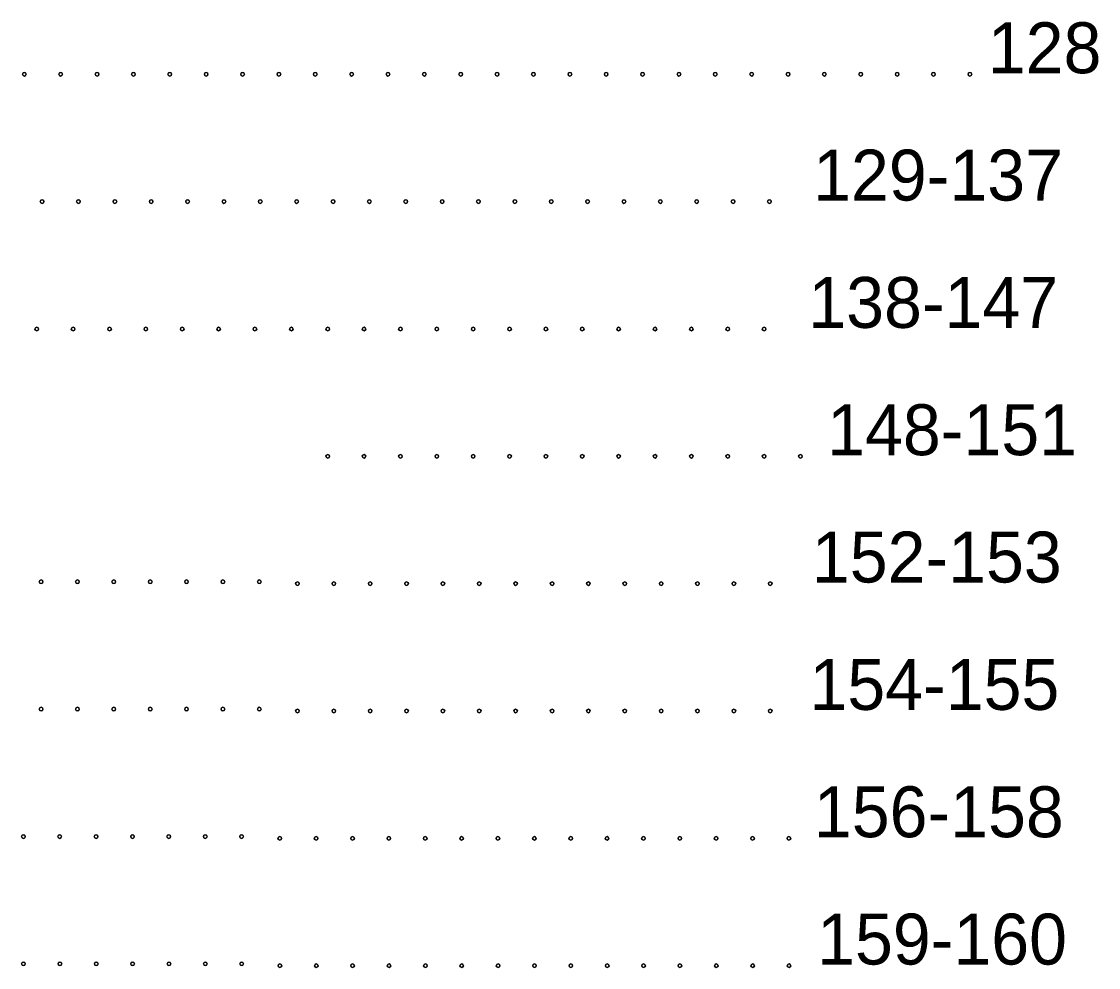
# Model space of a CAD drawing. Extents: x 0 to 1.42, y 0 to 0.92.
# Drawn here: x 0.7967 to 0.9201, y 0.5818 to 0.6902 of the extents above; entities that cross this region are included whole.
import ezdxf

# ---------------------------------------------------------------- set-up
doc = ezdxf.new("R2010")
doc.units = 0
doc.layers.add('DRAFT_Text-Notes', color=7, linetype='Continuous')

msp = doc.modelspace()

# ---------------------------------------------------------------- linework, layer by layer
at = {"layer": 'DRAFT_Text-Notes'}
for centre in [(0.79703, 0.68418), (0.80119, 0.68418), (0.80536, 0.68418), (0.80953, 0.68418), (0.81369, 0.68418), (0.81786, 0.68418), (0.82203, 0.68418), (0.82619, 0.68418), (0.83036, 0.68418), (0.83453, 0.68418), (0.83869, 0.68418), (0.84286, 0.68418), (0.84703, 0.68418), (0.85119, 0.68418), (0.85536, 0.68418), (0.85953, 0.68418), (0.86369, 0.68418), (0.86786, 0.68418), (0.87203, 0.68418), (0.87619, 0.68418), (0.88036, 0.68418), (0.88453, 0.68418), (0.88869, 0.68418), (0.89286, 0.68418), (0.89703, 0.68418), (0.90119, 0.68418), (0.90536, 0.68418), (0.79906, 0.66959), (0.80323, 0.66959), (0.8074, 0.66959), (0.81156, 0.66959), (0.81573, 0.66959), (0.8199, 0.66959), (0.82406, 0.66959), (0.82823, 0.66959), (0.8324, 0.66959), (0.83656, 0.66959), (0.84073, 0.66959), (0.8449, 0.66959), (0.84906, 0.66959), (0.85323, 0.66959), (0.8574, 0.66959), (0.86156, 0.66959), (0.86573, 0.66959), (0.8699, 0.66959), (0.87406, 0.66959), (0.87823, 0.66959), (0.8824, 0.66959), (0.79845, 0.65499), (0.80262, 0.65499), (0.80679, 0.65499), (0.81095, 0.65499), (0.81512, 0.65499), (0.81929, 0.65499), (0.82345, 0.65499), (0.82762, 0.65499), (0.83179, 0.65499), (0.83595, 0.65499), (0.84012, 0.65499), (0.84429, 0.65499), (0.84845, 0.65499), (0.85262, 0.65499), (0.85679, 0.65499), (0.86095, 0.65499), (0.86512, 0.65499), (0.86929, 0.65499), (0.87345, 0.65499), (0.87762, 0.65499), (0.88179, 0.65499), (0.83179, 0.6404), (0.83595, 0.6404), (0.84012, 0.6404), (0.84429, 0.6404), (0.84845, 0.6404), (0.85262, 0.6404), (0.85679, 0.6404), (0.86095, 0.6404), (0.86512, 0.6404), (0.86929, 0.6404), (0.87345, 0.6404), (0.87762, 0.6404), (0.88179, 0.6404), (0.88595, 0.6404), (0.79895, 0.62602), (0.80311, 0.62602), (0.80728, 0.62602), (0.81145, 0.62602), (0.81561, 0.62602), (0.81978, 0.62602), (0.82395, 0.62602), (0.82832, 0.62581), (0.83249, 0.62581), (0.83665, 0.62581), (0.84082, 0.62581), (0.84499, 0.62581), (0.84915, 0.62581), (0.85332, 0.62581), (0.85749, 0.62581), (0.86165, 0.62581), (0.86582, 0.62581), (0.86999, 0.62581), (0.87415, 0.62581), (0.87832, 0.62581), (0.88249, 0.62581), (0.79895, 0.61143), (0.80311, 0.61143), (0.80728, 0.61143), (0.81145, 0.61143), (0.81561, 0.61143), (0.81978, 0.61143), (0.82395, 0.61143), (0.82832, 0.61122), (0.83249, 0.61122), (0.83665, 0.61122), (0.84082, 0.61122), (0.84499, 0.61122), (0.84915, 0.61122), (0.85332, 0.61122), (0.85749, 0.61122), (0.86165, 0.61122), (0.86582, 0.61122), (0.86999, 0.61122), (0.87415, 0.61122), (0.87832, 0.61122), (0.88249, 0.61122), (0.79692, 0.59683), (0.80108, 0.59683), (0.80525, 0.59683), (0.80942, 0.59683), (0.81358, 0.59683), (0.81775, 0.59683), (0.82192, 0.59683), (0.82629, 0.59662), (0.83046, 0.59662), (0.83463, 0.59662), (0.83879, 0.59662), (0.84296, 0.59662), (0.84713, 0.59662), (0.85129, 0.59662), (0.85546, 0.59662), (0.85963, 0.59662), (0.86379, 0.59662), (0.86796, 0.59662), (0.87213, 0.59662), (0.87629, 0.59662), (0.88046, 0.59662), (0.88463, 0.59662), (0.79693, 0.58224), (0.8011, 0.58224), (0.80527, 0.58224), (0.80943, 0.58224), (0.8136, 0.58224), (0.81777, 0.58224), (0.82193, 0.58224), (0.82631, 0.58203), (0.83048, 0.58203), (0.83464, 0.58203), (0.83881, 0.58203), (0.84298, 0.58203), (0.84714, 0.58203), (0.85131, 0.58203), (0.85548, 0.58203), (0.85964, 0.58203), (0.86381, 0.58203), (0.86798, 0.58203), (0.87214, 0.58203), (0.87631, 0.58203), (0.88048, 0.58203), (0.88464, 0.58203)]:
    msp.add_circle(centre, 0.000208, dxfattribs=at)
for centre, start, end in [((0.79703, 0.68418), 0, 180), ((0.79703, 0.68418), 180, 0), ((0.80119, 0.68418), 0, 180), ((0.80119, 0.68418), 180, 0), ((0.80536, 0.68418), 0, 180), ((0.80536, 0.68418), 180, 0), ((0.80953, 0.68418), 0, 180), ((0.80953, 0.68418), 180, 0), ((0.81369, 0.68418), 0, 180), ((0.81369, 0.68418), 180, 0), ((0.81786, 0.68418), 0, 180), ((0.81786, 0.68418), 180, 0), ((0.82203, 0.68418), 0, 180), ((0.82203, 0.68418), 180, 0), ((0.82619, 0.68418), 0, 180), ((0.82619, 0.68418), 180, 0), ((0.83036, 0.68418), 0, 180), ((0.83036, 0.68418), 180, 0), ((0.83453, 0.68418), 0, 180), ((0.83453, 0.68418), 180, 0), ((0.83869, 0.68418), 0, 180), ((0.83869, 0.68418), 180, 0), ((0.84286, 0.68418), 0, 180), ((0.84286, 0.68418), 180, 0), ((0.84703, 0.68418), 0, 180), ((0.84703, 0.68418), 180, 0), ((0.85119, 0.68418), 0, 180), ((0.85119, 0.68418), 180, 0), ((0.85536, 0.68418), 0, 180), ((0.85536, 0.68418), 180, 0), ((0.85953, 0.68418), 0, 180), ((0.85953, 0.68418), 180, 0), ((0.86369, 0.68418), 0, 180), ((0.86369, 0.68418), 180, 0), ((0.86786, 0.68418), 0, 180), ((0.86786, 0.68418), 180, 0), ((0.87203, 0.68418), 0, 180), ((0.87203, 0.68418), 180, 0), ((0.87619, 0.68418), 0, 180), ((0.87619, 0.68418), 180, 0), ((0.88036, 0.68418), 0, 180), ((0.88036, 0.68418), 180, 0), ((0.88453, 0.68418), 0, 180), ((0.88453, 0.68418), 180, 0), ((0.88869, 0.68418), 0, 180), ((0.88869, 0.68418), 180, 0), ((0.89286, 0.68418), 0, 180), ((0.89286, 0.68418), 180, 0), ((0.89703, 0.68418), 0, 180), ((0.89703, 0.68418), 180, 0), ((0.90119, 0.68418), 0, 180), ((0.90119, 0.68418), 180, 0), ((0.90536, 0.68418), 0, 180), ((0.90536, 0.68418), 180, 0), ((0.79906, 0.66959), 0, 180), ((0.79906, 0.66959), 180, 0), ((0.80323, 0.66959), 0, 180), ((0.80323, 0.66959), 180, 0), ((0.8074, 0.66959), 0, 180), ((0.8074, 0.66959), 180, 0), ((0.81156, 0.66959), 0, 180), ((0.81156, 0.66959), 180, 0), ((0.81573, 0.66959), 0, 180), ((0.81573, 0.66959), 180, 0), ((0.8199, 0.66959), 0, 180), ((0.8199, 0.66959), 180, 0), ((0.82406, 0.66959), 0, 180), ((0.82406, 0.66959), 180, 0), ((0.82823, 0.66959), 0, 180), ((0.82823, 0.66959), 180, 0), ((0.8324, 0.66959), 0, 180), ((0.8324, 0.66959), 180, 0), ((0.83656, 0.66959), 0, 180), ((0.83656, 0.66959), 180, 0), ((0.84073, 0.66959), 0, 180), ((0.84073, 0.66959), 180, 0), ((0.8449, 0.66959), 0, 180), ((0.8449, 0.66959), 180, 0), ((0.84906, 0.66959), 0, 180), ((0.84906, 0.66959), 180, 0), ((0.85323, 0.66959), 0, 180), ((0.85323, 0.66959), 180, 0), ((0.8574, 0.66959), 0, 180), ((0.8574, 0.66959), 180, 0), ((0.86156, 0.66959), 0, 180), ((0.86156, 0.66959), 180, 0), ((0.86573, 0.66959), 0, 180), ((0.86573, 0.66959), 180, 0), ((0.8699, 0.66959), 0, 180), ((0.8699, 0.66959), 180, 0), ((0.87406, 0.66959), 0, 180), ((0.87406, 0.66959), 180, 0), ((0.87823, 0.66959), 0, 180), ((0.87823, 0.66959), 180, 0), ((0.8824, 0.66959), 0, 180), ((0.8824, 0.66959), 180, 0), ((0.79845, 0.65499), 0, 180), ((0.80262, 0.65499), 0, 180), ((0.80679, 0.65499), 0, 180), ((0.81095, 0.65499), 0, 180), ((0.81512, 0.65499), 0, 180), ((0.81929, 0.65499), 0, 180), ((0.82345, 0.65499), 0, 180), ((0.82762, 0.65499), 0, 180), ((0.83179, 0.65499), 0, 180), ((0.83595, 0.65499), 0, 180), ((0.84012, 0.65499), 0, 180), ((0.84429, 0.65499), 0, 180), ((0.84845, 0.65499), 0, 180), ((0.85262, 0.65499), 0, 180), ((0.85679, 0.65499), 0, 180), ((0.86095, 0.65499), 0, 180), ((0.86512, 0.65499), 0, 180), ((0.86929, 0.65499), 0, 180), ((0.87345, 0.65499), 0, 180), ((0.87762, 0.65499), 0, 180), ((0.88179, 0.65499), 0, 180), ((0.79845, 0.65499), 180, 0), ((0.80262, 0.65499), 180, 0), ((0.80679, 0.65499), 180, 0), ((0.81095, 0.65499), 180, 0), ((0.81512, 0.65499), 180, 0), ((0.81929, 0.65499), 180, 0), ((0.82345, 0.65499), 180, 0), ((0.82762, 0.65499), 180, 0), ((0.83179, 0.65499), 180, 0), ((0.83595, 0.65499), 180, 0), ((0.84012, 0.65499), 180, 0), ((0.84429, 0.65499), 180, 0), ((0.84845, 0.65499), 180, 0), ((0.85262, 0.65499), 180, 0), ((0.85679, 0.65499), 180, 0), ((0.86095, 0.65499), 180, 0), ((0.86512, 0.65499), 180, 0), ((0.86929, 0.65499), 180, 0), ((0.87345, 0.65499), 180, 0), ((0.87762, 0.65499), 180, 0), ((0.88179, 0.65499), 180, 0), ((0.83179, 0.6404), 0, 180), ((0.83179, 0.6404), 180, 0), ((0.83595, 0.6404), 0, 180), ((0.83595, 0.6404), 180, 0), ((0.84012, 0.6404), 0, 180), ((0.84012, 0.6404), 180, 0), ((0.84429, 0.6404), 0, 180), ((0.84429, 0.6404), 180, 0), ((0.84845, 0.6404), 0, 180), ((0.84845, 0.6404), 180, 0), ((0.85262, 0.6404), 0, 180), ((0.85262, 0.6404), 180, 0), ((0.85679, 0.6404), 0, 180), ((0.85679, 0.6404), 180, 0), ((0.86095, 0.6404), 0, 180), ((0.86095, 0.6404), 180, 0), ((0.86512, 0.6404), 0, 180), ((0.86512, 0.6404), 180, 0), ((0.86929, 0.6404), 0, 180), ((0.86929, 0.6404), 180, 0), ((0.87345, 0.6404), 0, 180), ((0.87345, 0.6404), 180, 0), ((0.87762, 0.6404), 0, 180), ((0.87762, 0.6404), 180, 0), ((0.88179, 0.6404), 0, 180), ((0.88179, 0.6404), 180, 0), ((0.88595, 0.6404), 0, 180), ((0.88595, 0.6404), 180, 0), ((0.79895, 0.62602), 0, 180), ((0.79895, 0.62602), 180, 0), ((0.80311, 0.62602), 0, 180), ((0.80311, 0.62602), 180, 0), ((0.80728, 0.62602), 0, 180), ((0.80728, 0.62602), 180, 0), ((0.81145, 0.62602), 0, 180), ((0.81145, 0.62602), 180, 0), ((0.81561, 0.62602), 0, 180), ((0.81561, 0.62602), 180, 0), ((0.81978, 0.62602), 0, 180), ((0.81978, 0.62602), 180, 0), ((0.82395, 0.62602), 0, 180), ((0.82395, 0.62602), 180, 0), ((0.82832, 0.62581), 0, 180), ((0.82832, 0.62581), 180, 0), ((0.83249, 0.62581), 0, 180), ((0.83249, 0.62581), 180, 0), ((0.83665, 0.62581), 0, 180), ((0.83665, 0.62581), 180, 0), ((0.84082, 0.62581), 0, 180), ((0.84082, 0.62581), 180, 0), ((0.84499, 0.62581), 0, 180), ((0.84499, 0.62581), 180, 0), ((0.84915, 0.62581), 0, 180), ((0.84915, 0.62581), 180, 0), ((0.85332, 0.62581), 0, 180), ((0.85332, 0.62581), 180, 0), ((0.85749, 0.62581), 0, 180), ((0.85749, 0.62581), 180, 0), ((0.86165, 0.62581), 0, 180), ((0.86165, 0.62581), 180, 0), ((0.86582, 0.62581), 0, 180), ((0.86582, 0.62581), 180, 0), ((0.86999, 0.62581), 0, 180), ((0.86999, 0.62581), 180, 0), ((0.87415, 0.62581), 0, 180), ((0.87415, 0.62581), 180, 0), ((0.87832, 0.62581), 0, 180), ((0.87832, 0.62581), 180, 0), ((0.88249, 0.62581), 0, 180), ((0.88249, 0.62581), 180, 0), ((0.79895, 0.61143), 0, 180), ((0.79895, 0.61143), 180, 0), ((0.80311, 0.61143), 0, 180), ((0.80311, 0.61143), 180, 0), ((0.80728, 0.61143), 0, 180), ((0.80728, 0.61143), 180, 0), ((0.81145, 0.61143), 0, 180), ((0.81145, 0.61143), 180, 0), ((0.81561, 0.61143), 0, 180), ((0.81561, 0.61143), 180, 0), ((0.81978, 0.61143), 0, 180), ((0.81978, 0.61143), 180, 0), ((0.82395, 0.61143), 0, 180), ((0.82395, 0.61143), 180, 0), ((0.82832, 0.61122), 0, 180), ((0.82832, 0.61122), 180, 0), ((0.83249, 0.61122), 0, 180), ((0.83249, 0.61122), 180, 0), ((0.83665, 0.61122), 0, 180), ((0.83665, 0.61122), 180, 0), ((0.84082, 0.61122), 0, 180), ((0.84082, 0.61122), 180, 0), ((0.84499, 0.61122), 0, 180), ((0.84499, 0.61122), 180, 0), ((0.84915, 0.61122), 0, 180), ((0.84915, 0.61122), 180, 0), ((0.85332, 0.61122), 0, 180), ((0.85332, 0.61122), 180, 0), ((0.85749, 0.61122), 0, 180), ((0.85749, 0.61122), 180, 0), ((0.86165, 0.61122), 0, 180), ((0.86165, 0.61122), 180, 0), ((0.86582, 0.61122), 0, 180), ((0.86582, 0.61122), 180, 0), ((0.86999, 0.61122), 0, 180), ((0.86999, 0.61122), 180, 0), ((0.87415, 0.61122), 0, 180), ((0.87415, 0.61122), 180, 0), ((0.87832, 0.61122), 0, 180), ((0.87832, 0.61122), 180, 0), ((0.88249, 0.61122), 0, 180), ((0.88249, 0.61122), 180, 0), ((0.79692, 0.59683), 0, 180), ((0.79692, 0.59683), 180, 0), ((0.80108, 0.59683), 0, 180), ((0.80108, 0.59683), 180, 0), ((0.80525, 0.59683), 0, 180), ((0.80525, 0.59683), 180, 0), ((0.80942, 0.59683), 0, 180), ((0.80942, 0.59683), 180, 0), ((0.81358, 0.59683), 0, 180), ((0.81358, 0.59683), 180, 0), ((0.81775, 0.59683), 0, 180), ((0.81775, 0.59683), 180, 0), ((0.82192, 0.59683), 0, 180), ((0.82192, 0.59683), 180, 0), ((0.82629, 0.59662), 0, 180), ((0.82629, 0.59662), 180, 0), ((0.83046, 0.59662), 0, 180), ((0.83046, 0.59662), 180, 0), ((0.83463, 0.59662), 0, 180), ((0.83463, 0.59662), 180, 0), ((0.83879, 0.59662), 0, 180), ((0.83879, 0.59662), 180, 0), ((0.84296, 0.59662), 0, 180), ((0.84296, 0.59662), 180, 0), ((0.84713, 0.59662), 0, 180), ((0.84713, 0.59662), 180, 0), ((0.85129, 0.59662), 0, 180), ((0.85129, 0.59662), 180, 0), ((0.85546, 0.59662), 0, 180), ((0.85546, 0.59662), 180, 0), ((0.85963, 0.59662), 0, 180), ((0.85963, 0.59662), 180, 0), ((0.86379, 0.59662), 0, 180), ((0.86379, 0.59662), 180, 0), ((0.86796, 0.59662), 0, 180), ((0.86796, 0.59662), 180, 0), ((0.87213, 0.59662), 0, 180), ((0.87213, 0.59662), 180, 0), ((0.87629, 0.59662), 0, 180), ((0.87629, 0.59662), 180, 0), ((0.88046, 0.59662), 0, 180), ((0.88046, 0.59662), 180, 0), ((0.88463, 0.59662), 0, 180), ((0.88463, 0.59662), 180, 0), ((0.79693, 0.58224), 0, 180), ((0.8011, 0.58224), 0, 180), ((0.80527, 0.58224), 0, 180), ((0.80943, 0.58224), 0, 180), ((0.8136, 0.58224), 0, 180), ((0.81777, 0.58224), 0, 180), ((0.82193, 0.58224), 0, 180), ((0.79693, 0.58224), 180, 0), ((0.8011, 0.58224), 180, 0), ((0.80527, 0.58224), 180, 0), ((0.80943, 0.58224), 180, 0), ((0.8136, 0.58224), 180, 0), ((0.81777, 0.58224), 180, 0), ((0.82193, 0.58224), 180, 0), ((0.82631, 0.58203), 0, 180), ((0.82631, 0.58203), 180, 0), ((0.83048, 0.58203), 0, 180), ((0.83048, 0.58203), 180, 0), ((0.83464, 0.58203), 0, 180), ((0.83464, 0.58203), 180, 0), ((0.83881, 0.58203), 0, 180), ((0.83881, 0.58203), 180, 0), ((0.84298, 0.58203), 0, 180), ((0.84298, 0.58203), 180, 0), ((0.84714, 0.58203), 0, 180), ((0.84714, 0.58203), 180, 0), ((0.85131, 0.58203), 0, 180), ((0.85131, 0.58203), 180, 0), ((0.85548, 0.58203), 0, 180), ((0.85548, 0.58203), 180, 0), ((0.85964, 0.58203), 0, 180), ((0.85964, 0.58203), 180, 0), ((0.86381, 0.58203), 0, 180), ((0.86381, 0.58203), 180, 0), ((0.86798, 0.58203), 0, 180), ((0.86798, 0.58203), 180, 0), ((0.87214, 0.58203), 0, 180), ((0.87214, 0.58203), 180, 0), ((0.87631, 0.58203), 0, 180), ((0.87631, 0.58203), 180, 0), ((0.88048, 0.58203), 0, 180), ((0.88048, 0.58203), 180, 0), ((0.88464, 0.58203), 0, 180), ((0.88464, 0.58203), 180, 0)]:
    msp.add_arc(centre, 0.000208, start, end, dxfattribs=at)

# ---------------------------------------------------------------- texts
for s, p in [('128', (0.90742, 0.6843)), ('129-137', (0.8874, 0.66971)), ('138-147', (0.88685, 0.65512)), ('148-151', (0.88901, 0.64053)), ('152-153', (0.88726, 0.62594)), ('154-155', (0.88698, 0.61134)), ('156-158', (0.88749, 0.59675)), ('159-160', (0.88786, 0.58216))]:
    msp.add_text(s, height=0.005833, dxfattribs=at).set_placement(p)

doc.saveas('drawing.dxf')
